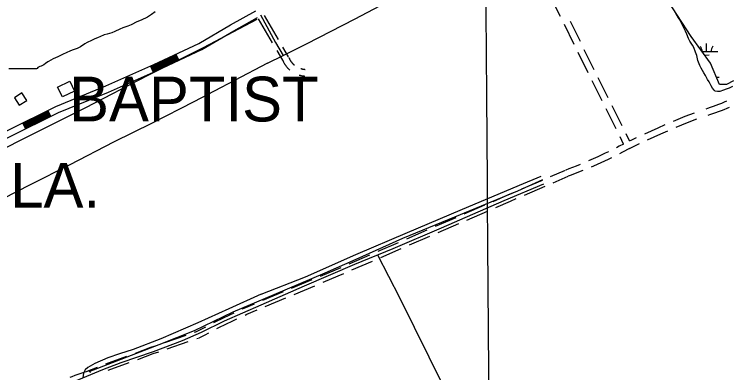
# Model space of a CAD drawing. Extents: x 3540316 to 3578335, y 553172 to 578787.
# Drawn here: x 3558126 to 3561322, y 570951 to 572552 of the extents above; entities that cross this region are included whole.
import ezdxf

# ---------------------------------------------------------------- set-up
doc = ezdxf.new("R2010")
doc.units = 0
for name, color, linetype in [('V-BLDG-OTLN', 7, 'Continuous'), ('V-DTCH-CNTR', 7, 'Continuous'), ('V-GRID-MAJR', 7, 'Continuous'), ('V-ROAD-CNTR', 7, 'Continuous'), ('V-SITE-VEGE', 7, 'Continuous'), ('V-TOPO-GNAM-IDEN', 7, 'Continuous'), ('V-TOPO-SHOR', 7, 'Continuous'), ('V-WETL-SWMP', 7, 'Continuous')]:
    doc.layers.add(name, color=color, linetype=linetype)

msp = doc.modelspace()

# ---------------------------------------------------------------- linework, layer by layer
at = {"layer": 'V-BLDG-OTLN'}
for points in [[(3558318.69, 572226.8910000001), (3558373.2090000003, 572253.046), (3558394.552, 572208.557), (3558341.146, 572182.937)], [(3558126.0237096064, 572179.6536142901), (3558147.232667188, 572145.7386821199), (3558181.147599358, 572166.9476397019), (3558159.9386417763, 572200.862571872)]]:
    msp.add_lwpolyline(points, close=True, dxfattribs=at)
at = {"layer": 'V-DTCH-CNTR'}
for points in [[(3559256.1410000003, 572333.684), (3559326.086, 572368.133), (3559430.487, 572419.554), (3559648.018, 572531.426), (3559758.3310000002, 572590.104)], [(3559225.585, 572550.5380000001), (3559292.614, 572426.733), (3559326.086, 572368.133)], [(3559256.1410000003, 572333.684), (3559109.42, 572255.979), (3558928.054, 572161.242), (3558741.958, 572066.4400000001), (3558569.328, 571981.282), (3558373.865, 571879.849), (3558197.161, 571789.905), (3558012.239, 571695.709), (3557833.781, 571604.561), (3557662.365, 571517.056), (3557481.531, 571426.465), (3557392.3340000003, 571378.525), (3557367.77, 571366.442)], [(3559227.94, 571300.894), (3559425.982, 571378.929), (3559651.383, 571479.115), (3559881.811, 571576.651), (3560117.636, 571677.435), (3560382.795, 571789.057), (3560479.315, 571828.493)], [(3559228.5870000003, 571254.197), (3559422.453, 571338.98), (3559647.444, 571435.986), (3559818.383, 571505.935), (3560034.821, 571598.2880000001), (3560314.353, 571720.087), (3560490.669, 571794.6460000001)], [(3559748.14, 571477.192), (3559846.9420000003, 571286.242), (3559978.059, 571021.807), (3560111.9960000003, 570750.154), (3560179.201, 570609.901), (3560180.6550000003, 570606.867), (3560197.844, 570577.622)], [(3559227.94, 571300.894), (3559083.413, 571235.634), (3558945.3510000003, 571172.83), (3558779.608, 571102.549), (3558656.12, 571054.726), (3558594.909, 571034.961), (3558543.716, 571017.698), (3558485.542, 570992.061), (3558454.454, 570974.488), (3558442.194, 570963.084), (3558435.307, 570948.21), (3558432.329, 570927.64)], [(3557575.757, 570603.587), (3557675.296, 570630.387), (3557796.173, 570653.343), (3557936.975, 570688.99), (3558008.823, 570708.903), (3558057.039, 570727.8960000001), (3558095.828, 570744.397), (3558161.5300000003, 570781.3690000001), (3558223.046, 570821.832), (3558284.011, 570859.329), (3558345.631, 570892.107), (3558413.473, 570919.648), (3558432.329, 570927.64), (3558521.6180000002, 570965.485), (3558603.378, 570995.586), (3558746.9280000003, 571046.051), (3558876.327, 571093.956), (3558962.583, 571132.395), (3559065.235, 571182.175), (3559228.5870000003, 571254.197)]]:
    msp.add_lwpolyline(points, dxfattribs=at)
at = {"layer": 'V-GRID-MAJR'}
msp.add_spline([(3560340.269, 558695.246), (3560293.573, 564752.677), (3560246.85, 570813.577), (3560200.127, 576874.4940000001), (3560200.1, 576877.944)], degree=3, dxfattribs=at)
at = {"layer": 'V-ROAD-CNTR'}
for p, q in [((3558847.243267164, 572373.7572260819), (3558860.0172416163, 572346.61328037)), ((3558734.2974930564, 572320.972331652), (3558746.481468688, 572293.557386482)), ((3558274.773412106, 572122.5717284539), (3558288.109385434, 572095.6987821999)), ((3558162.8026360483, 572067.0068395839), (3558176.138609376, 572040.1338933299))]:
    msp.add_line(p, q, dxfattribs=at)
for points in [[(3560565.374830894, 572542.1508892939), (3560521.0109196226, 572631.771710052)], [(3557247.45346675, 571612.7707480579), (3558310.853339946, 572140.475692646), (3558534.98089169, 572232.387508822), (3558748.271465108, 572327.182319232), (3558949.29506306, 572421.781130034), (3559091.24977915, 572504.5889644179), (3559204.733552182, 572568.424836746)], [(3559305.5393505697, 572439.4780946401), (3559243.022475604, 572546.1358813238)], [(3557229.860501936, 571570.5498324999), (3558323.227315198, 572113.125747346), (3558546.766868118, 572204.7955640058), (3558760.7514401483, 572299.900373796), (3558963.2670351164, 572395.201183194), (3559106.1617493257, 572478.5570164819), (3559211.7715381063, 572537.9618976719)], [(3559279.6574023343, 572424.30812498), (3559216.326528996, 572532.354908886)], [(3560654.3706529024, 572429.9921136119), (3560610.0067416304, 572519.6129343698)], [(3560627.4847066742, 572416.6821402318), (3560583.120795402, 572506.30296099)], [(3559325.168311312, 572346.6632802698), (3559299.8843618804, 572389.7991939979)], [(3559351.0502595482, 572361.83324993), (3559325.766310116, 572404.9691636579)], [(3560689.594582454, 572291.2143911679), (3560645.2306711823, 572380.834211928)], [(3560716.480528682, 572304.524364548), (3560672.1166174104, 572394.144185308)], [(3558735.514490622, 572318.2303371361), (3558749.5194626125, 572324.454324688), (3558848.52026461, 572371.0422315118)], [(3558736.732488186, 572315.4883426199), (3558750.7674601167, 572321.726330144), (3558849.7972620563, 572368.3272369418)], [(3558737.95048575, 572312.7473481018), (3558752.0154576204, 572318.9983355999), (3558851.0742595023, 572365.61324237)], [(3558739.1694833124, 572310.0053535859), (3558753.263455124, 572316.269341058), (3558852.3522569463, 572362.8982477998)], [(3558740.387480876, 572307.2643590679), (3558754.5114526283, 572313.541346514), (3558853.6292543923, 572360.184253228)], [(3558741.6054784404, 572304.5233645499), (3558755.7594501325, 572310.8133519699), (3558854.906251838, 572357.4702586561)], [(3558742.824476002, 572301.781370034), (3558757.007447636, 572308.0843574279), (3558856.184249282, 572354.7552640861)], [(3558744.0424735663, 572299.0403755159), (3558758.25544514, 572305.3563628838), (3558857.461246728, 572352.0412695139)], [(3558745.2604711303, 572296.2983809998), (3558759.503442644, 572302.6283683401), (3558858.738244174, 572349.3262749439)], [(3559324.122313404, 572348.8282759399), (3559324.8023120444, 572347.07327945), (3559325.56931051, 572345.21828316), (3559326.3353089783, 572343.4542866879), (3559327.142307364, 572341.6512902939), (3559328.0103056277, 572339.8252939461), (3559328.865303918, 572338.10829738), (3559329.761302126, 572336.35330089), (3559330.7223002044, 572334.5763044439), (3559331.685298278, 572332.869307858), (3559332.6882962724, 572331.1573112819), (3559333.6962942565, 572329.5073145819), (3559334.7372921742, 572327.8483179), (3559335.853289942, 572326.150321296), (3559336.973287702, 572324.5203245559), (3559338.091285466, 572322.9483276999), (3559339.253283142, 572321.35833088), (3559340.4612807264, 572319.77833404), (3559341.6852782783, 572318.2233371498), (3559342.9512757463, 572316.687340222), (3559344.202273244, 572315.2123431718), (3559345.5142706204, 572313.7153461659), (3559346.858267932, 572312.2433491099), (3559348.1952652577, 572310.8303519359), (3559349.5742625, 572309.4123547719), (3559350.9892596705, 572308.0203575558), (3559352.410256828, 572306.660360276), (3559353.847253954, 572305.3383629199), (3559355.337250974, 572304.0013655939), (3559356.861247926, 572302.705368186), (3559357.213247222, 572302.4133687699)], [(3559352.096257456, 572359.6682542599), (3559352.6562563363, 572358.2232571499), (3559353.1932552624, 572356.9222597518), (3559353.787254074, 572355.5542624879), (3559354.3842528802, 572354.2192651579), (3559354.986251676, 572352.9532676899), (3559355.651250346, 572351.61827036), (3559356.317249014, 572350.3152729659), (3559356.9842476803, 572349.0822754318), (3559357.697246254, 572347.817277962), (3559358.432244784, 572346.561280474), (3559359.2042432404, 572345.2992829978), (3559359.97924169, 572344.0622854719), (3559360.7512401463, 572342.8902878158), (3559361.563238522, 572341.70829018), (3559362.42923679, 572340.490292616), (3559363.2832350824, 572339.320294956), (3559364.163233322, 572338.170297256), (3559365.04923155, 572337.0452995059), (3559365.9692297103, 572335.929301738), (3559366.9242278, 572334.8023039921), (3559367.8742259, 572333.7193061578), (3559368.83422398, 572332.6673082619), (3559369.8472219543, 572331.5963104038), (3559370.8502199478, 572330.5643124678), (3559371.881217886, 572329.5503144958), (3559372.938215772, 572328.5383165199), (3559374.0192136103, 572327.5443185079), (3559375.0752114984, 572326.5973204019), (3559376.15920933, 572325.6753222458), (3559376.371208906, 572325.499322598)], [(3559406.0411495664, 572309.527354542), (3559406.627148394, 572309.354354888), (3559408.062145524, 572308.9483557), (3559409.420142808, 572308.5893564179), (3559410.8171400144, 572308.2563570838), (3559412.2851370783, 572307.9233577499), (3559413.6781342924, 572307.63335833), (3559415.0791314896, 572307.3713588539), (3559416.5161286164, 572307.1293593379), (3559417.99412566, 572306.9033597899), (3559419.4061228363, 572306.7073601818), (3559420.8161200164, 572306.5473605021), (3559422.271117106, 572306.4013607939), (3559423.7341141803, 572306.284361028), (3559425.185111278, 572306.187361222), (3559425.445110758, 572306.1763612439)], [(3559397.5151666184, 572280.765412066), (3559398.285165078, 572280.536412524), (3559400.142161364, 572280.0124135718), (3559402.098157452, 572279.4934146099), (3559404.023153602, 572279.0344155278), (3559405.9091498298, 572278.6074163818), (3559407.8661459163, 572278.199417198), (3559409.831141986, 572277.8334179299), (3559411.7581381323, 572277.507418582), (3559413.666134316, 572277.2174191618), (3559415.6441303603, 572276.941419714), (3559417.632126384, 572276.715420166), (3559419.5811224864, 572276.5214205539), (3559421.5381185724, 572276.3644208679), (3559423.5091146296, 572276.23342113), (3559424.087113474, 572276.2064211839)], [(3560751.704458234, 572165.7466421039), (3560707.340546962, 572255.366462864)], [(3560778.590404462, 572179.0566154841), (3560734.22649319, 572268.676436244)], [(3561306.81034802, 572163.5156465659), (3561296.417368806, 572158.871655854), (3561284.253393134, 572153.750666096), (3561272.064417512, 572148.827675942), (3561259.763442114, 572144.0876854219), (3561247.441466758, 572139.622694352), (3561234.973491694, 572135.3587028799), (3561222.498516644, 572131.270711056), (3561215.052531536, 572129.0217155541)], [(3560813.814334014, 572040.2788930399), (3560769.450422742, 572129.8987138)], [(3560840.700280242, 572053.5888664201), (3560796.33636897, 572143.2086871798)], [(3561319.048323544, 572136.125701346), (3561308.359344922, 572131.3497108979), (3561295.6933702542, 572126.0167215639), (3561283.076395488, 572120.9197317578), (3561270.2674211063, 572115.985741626), (3561257.4054468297, 572111.324750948), (3561244.4974726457, 572106.9107597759), (3561231.508498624, 572102.6547682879), (3561223.7305141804, 572100.30377299)], [(3558164.1346333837, 572064.3178449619), (3558276.105409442, 572119.8827338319)], [(3558165.4676307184, 572061.6308503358), (3558277.4384067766, 572117.1957392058)], [(3558166.80162805, 572058.9438557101), (3558278.772404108, 572114.5087445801)], [(3558168.1346253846, 572056.255861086), (3558280.105401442, 572111.820749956)], [(3558169.468622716, 572053.5688664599), (3558281.4393987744, 572109.1337553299)], [(3558170.802620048, 572050.8818718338), (3558282.773396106, 572106.4467607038)], [(3558172.135617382, 572048.1938772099), (3558284.10639344, 572103.7587660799)], [(3558173.4696147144, 572045.5068825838), (3558285.4403907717, 572101.0717714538)], [(3558174.802612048, 572042.8198879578), (3558286.7733881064, 572098.3847768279)], [(3561070.6228203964, 572075.051823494), (3561122.26571711, 572096.3857808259), (3561163.74563415, 572112.41374877)], [(3561082.076797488, 572047.3238789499), (3561133.401694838, 572068.525836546), (3561174.5596125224, 572084.4298047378)], [(3560942.00607763, 572018.6989361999), (3561001.6279583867, 572045.330882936), (3561033.619894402, 572059.195855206)], [(3560954.2420531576, 571991.306990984), (3561013.7099342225, 572017.8709378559), (3561045.5498705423, 572031.6699102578)], [(3560847.3122670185, 571972.612028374), (3560831.560298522, 572004.430964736)], [(3560874.0052136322, 571986.3100009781), (3560858.44624475, 572017.7409381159)], [(3560874.0052136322, 571986.3100009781), (3560882.105197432, 571990.272993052), (3560905.552150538, 572001.4059707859)], [(3560847.3122670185, 571972.612028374), (3560828.5073046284, 571962.4700486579), (3560815.96632971, 571956.0750614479)], [(3560873.5322145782, 571952.682068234), (3560895.13117138, 571963.2470471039), (3560918.4201248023, 571974.3060249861)], [(3560780.420400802, 571938.305096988), (3560765.31643101, 571930.927111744), (3560733.2014952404, 571915.6801422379), (3560700.920559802, 571901.263171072), (3560690.333580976, 571896.757180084)], [(3560874.0612135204, 571952.95406769), (3560842.4432767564, 571935.902101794), (3560829.59630245, 571929.3491148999)], [(3560793.588374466, 571911.3491508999), (3560778.3344049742, 571903.8971658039), (3560745.7534701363, 571888.430196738), (3560712.9125358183, 571873.7632260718), (3560702.0835574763, 571869.153235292)], [(3560653.610654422, 571881.3172109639), (3560635.629690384, 571873.8922258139), (3560602.6427563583, 571861.1672512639), (3560589.50178264, 571856.3392609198)], [(3560521.393918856, 571827.1023193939), (3560588.753784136, 571856.0412615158)], [(3560665.0606315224, 571853.587266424), (3560646.753668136, 571846.0282815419), (3560613.214735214, 571833.091307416), (3560599.847761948, 571828.17931724)], [(3560392.7621761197, 571771.8414299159), (3560484.6419923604, 571811.3133509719)], [(3560533.235895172, 571799.538374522), (3560600.5957604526, 571828.4773166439)], [(3560404.6041524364, 571744.277485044), (3560496.483968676, 571783.7494061)], [(3560264.188433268, 571716.2935410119), (3560329.894301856, 571744.8324839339), (3560356.0102496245, 571756.052461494)], [(3560276.140409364, 571688.7775960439), (3560341.7902780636, 571717.2925390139), (3560367.8522259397, 571728.4885166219)], [(3560135.7776900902, 571660.51965256), (3560227.4995066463, 571700.3585728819)], [(3560147.7296661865, 571633.003707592), (3560239.4514827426, 571672.8426279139)], [(3560007.366946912, 571604.7447641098), (3560099.088763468, 571644.5836844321)], [(3560019.318923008, 571577.2288191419), (3560111.040739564, 571617.0677394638)], [(3559878.9562037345, 571548.9708756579), (3559970.6780202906, 571588.80979598)], [(3559890.9081798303, 571521.4549306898), (3559982.6299963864, 571561.293851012)], [(3559750.545460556, 571493.1959872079), (3559842.267277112, 571533.0349075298)], [(3559762.4974366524, 571465.68004224), (3559854.219253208, 571505.5189625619)], [(3559622.1347173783, 571437.4220987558), (3559713.8565339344, 571477.2610190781)], [(3559634.086693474, 571409.9061537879), (3559725.8085100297, 571449.74507411)], [(3559493.5409745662, 571382.5502084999), (3559560.7278401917, 571410.7501520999), (3559585.4457907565, 571421.4861306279)], [(3559505.1509513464, 571354.888263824), (3559572.509816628, 571383.16020728), (3559597.3977668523, 571393.97018566)], [(3559364.4512327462, 571328.368316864), (3559456.658048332, 571367.07023946)], [(3559376.061209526, 571300.7063721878), (3559468.2680251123, 571339.4082947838)], [(3559235.361490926, 571274.1854252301), (3559327.5683065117, 571312.887347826)], [(3559246.971467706, 571246.5234805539), (3559339.178283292, 571285.2254031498)], [(3559143.862673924, 571235.4175027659), (3559151.868657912, 571239.1304953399)], [(3559152.3746569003, 571239.353494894), (3559198.478564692, 571258.704456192)], [(3559163.9846336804, 571211.6915502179), (3559210.088541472, 571231.0425115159)], [(3559017.1719273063, 571174.4636246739), (3559025.8629099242, 571178.927615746), (3559088.4107848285, 571209.701554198), (3559107.5747465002, 571218.589536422)], [(3559156.48464868, 571208.2015571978), (3559164.490632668, 571211.914549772)], [(3559030.877899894, 571147.777678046), (3559039.338882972, 571152.123669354), (3559101.34475896, 571182.6316083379), (3559120.1967212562, 571191.373590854)], [(3558937.116087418, 571133.1447073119), (3558963.9280337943, 571147.1196793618), (3558981.58999847, 571156.189661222)], [(3558798.7053642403, 571085.691802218), (3558893.2631751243, 571118.2307371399)], [(3558931.086099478, 571131.2457111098), (3558939.168083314, 571134.0267055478)], [(3558940.8480799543, 571102.8777678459), (3558948.93006379, 571105.6587622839)], [(3558950.9820596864, 571106.54076052), (3558977.714006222, 571120.4737326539), (3558995.295971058, 571129.503714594)], [(3558666.568628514, 571038.42589675), (3558735.7364901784, 571064.022845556), (3558760.882439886, 571072.6758282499)], [(3558808.467344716, 571057.323858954), (3558903.0251556, 571089.862793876)], [(3558676.98060769, 571010.289953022), (3558745.824470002, 571035.7669020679), (3558770.644420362, 571044.3078849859)], [(3558535.2708911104, 570989.8379939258), (3558629.054703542, 571024.5439245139)], [(3558451.060059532, 570957.6110583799), (3558497.756966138, 570975.4830226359)], [(3558545.682870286, 570961.7020501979), (3558639.466682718, 570996.4079807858)], [(3558374.694212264, 570930.515112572), (3558384.1661933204, 570934.3901048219), (3558397.61116643, 570939.6160943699), (3558411.1841392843, 570944.5330845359), (3558424.6841122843, 570949.254075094), (3558438.3400849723, 570953.7670660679), (3558452.044057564, 570957.949057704)]]:
    msp.add_lwpolyline(points, dxfattribs=at)
at = {"layer": 'V-SITE-VEGE'}
for p, q in [((3561092.491, 572536.9130000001), (3561082.404, 572554.792)), ((3561099.7490000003, 572525.549), (3561092.491, 572536.9130000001)), ((3561109.294, 572507.1190000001), (3561099.7490000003, 572525.549)), ((3561115.477, 572494.6460000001), (3561109.294, 572507.1190000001)), ((3561123.3850000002, 572476.192), (3561115.477, 572494.6460000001)), ((3561130.12, 572463.181), (3561123.3850000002, 572476.192)), ((3561138.044, 572443.637), (3561130.12, 572463.181)), ((3561144.223, 572431.709), (3561138.044, 572443.637)), ((3561154.842, 572414.385), (3561144.223, 572431.709)), ((3561161.004, 572403.551), (3561154.842, 572414.385)), ((3561168.934, 572383.456), (3561161.004, 572403.551)), ((3561174.0640000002, 572368.242), (3561168.934, 572383.456)), ((3561178.742, 572346.465), (3561174.0640000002, 572368.242)), ((3561188.349, 572323.669), (3561178.742, 572346.465)), ((3561194.536, 572311.1950000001), (3561188.349, 572323.669)), ((3561205.755, 572290.055), (3561194.536, 572311.1950000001)), ((3561213.015, 572278.693), (3561205.755, 572290.055)), ((3561223.1, 572260.814), (3561213.015, 572278.693)), ((3561229.807, 572249.988), (3561223.1, 572260.814)), ((3561239.328, 572233.1950000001), (3561229.807, 572249.988)), ((3561244.397, 572222.344), (3561239.328, 572233.1950000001)), ((3561251.634, 572212.618), (3561244.397, 572222.344)), ((3561318.6550000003, 572222.854), (3561305.63, 572217.21)), ((3561333.858, 572229.078), (3561318.6550000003, 572222.854)), ((3561256.603, 572208.866), (3561251.634, 572212.618)), ((3561267.007, 572206.829), (3561256.603, 572208.866)), ((3561277.38, 572206.976), (3561267.007, 572206.829)), ((3561294.227, 572212.678), (3561277.38, 572206.976)), ((3561305.63, 572217.21), (3561294.227, 572212.6780000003))]:
    msp.add_line(p, q, dxfattribs=at)
for points in [[(3558754.909, 572562.6950000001), (3558738.685, 572551.546), (3558720.8310000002, 572539.823), (3558692.636, 572525.772), (3558673.6350000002, 572517.856), (3558648.143, 572505.48), (3558632.949, 572498.712), (3558611.2120000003, 572491.304), (3558596.5500000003, 572485.635), (3558574.305, 572475.4890000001), (3558561.2770000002, 572469.845), (3558541.156, 572464.098), (3558527.563, 572460.082), (3558507.482, 572451.063), (3558500.417, 572448.775), (3558482.501, 572441.4230000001), (3558470.029, 572435.238), (3558451.597, 572425.692), (3558440.216, 572419.524), (3558420.741, 572406.687), (3558407.1920000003, 572399.3960000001), (3558388.715, 572393.127), (3558376.22, 572388.58), (3558357.235, 572379.573), (3558344.21, 572373.929), (3558325.778, 572364.383), (3558319.804, 572362.1140000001), (3558299.1890000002, 572352.5380000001), (3558279.151, 572340.786), (3558275.352, 572339.095), (3558265.079, 572331.849), (3558256.967, 572326.272), (3558245.586, 572320.105), (3558239.059, 572318.375), (3558230.931, 572313.89), (3558227.701, 572310.568), (3558225.54, 572308.899), (3558150.184, 572308.919)], [(3558150.184, 572308.919), (3558126.159, 572308.577), (3558100.492, 572308.762)]]:
    msp.add_lwpolyline(points, dxfattribs=at)
at = {"layer": 'V-TOPO-SHOR'}
msp.add_line((3558462.605, 570956.819), (3558464.487, 570951.857), dxfattribs=at)
for points in [[(3557263.363, 571588.404), (3557430.472, 571672.8150000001), (3557709.348, 571809.1190000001), (3557748.1410000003, 571824.625), (3557768.933, 571829.902), (3557817.407, 571834.201), (3557857.2260000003, 571841.103), (3557884.29, 571851.91), (3557951.844, 571886.863), (3558147.774, 571986.187), (3558444.615, 572135.443), (3558721.1240000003, 572278.973), (3558970.22, 572403.979), (3559211.14, 572529.782)], [(3558459.3850000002, 570955.578), (3558772.946, 571076.49), (3558929.915, 571139.8960000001), (3559102.9450000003, 571222.574), (3559286.019, 571300.404), (3559514.197, 571396.546), (3559653.498, 571458.346), (3559861.7490000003, 571552.4), (3560068.771, 571636.909), (3560375.002, 571763.162), (3560486.784, 571814.149)]]:
    msp.add_lwpolyline(points, dxfattribs=at)
at = {"layer": 'V-WETL-SWMP'}
for p, q in [((3561149.3609553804, 572452.3016130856), (3561046.691957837, 572610.2525793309)), ((3561236.2339535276, 572333.8376385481), (3561149.3609553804, 572452.3016130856)), ((3561218.384477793, 572385.7655204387), (3561218.1069674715, 572421.7644471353)), ((3561198.267486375, 572385.610441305), (3561268.382992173, 572386.1509521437)), ((3561209.5201991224, 572370.2657300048), (3561230.503072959, 572370.4274841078)), ((3561275.721952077, 572239.0666584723), (3561236.2339535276, 572333.8376385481)), ((3561262.5536145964, 572270.6705962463), (3561273.864677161, 572270.7577916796)), ((3561338.9019522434, 572254.8616561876), (3561307.311952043, 572239.0666589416)), ((3561307.311952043, 572239.0666589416), (3561275.721952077, 572239.0666584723))]:
    msp.add_line(p, q, dxfattribs=at)
for centre, radius, start, end in [((3561163.1395230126, 572385.8144618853), 35.24628790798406, 359.6698565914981, 41.21351492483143), ((3561273.6221124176, 572386.6661570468), 35.24628790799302, 139.6698534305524, 181.21351176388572)]:
    msp.add_arc(centre, radius, start, end, dxfattribs=at)

# ---------------------------------------------------------------- texts
at = {"layer": 'V-TOPO-GNAM-IDEN'}
for s, p in [('BAPTIST', (3558370.394992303, 572073.4995217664)), ('LA.', (3558107.4318114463, 571688.2936018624))]:
    msp.add_text(s, height=199.99959800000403, dxfattribs=at).set_placement(p)

doc.saveas('drawing.dxf')
